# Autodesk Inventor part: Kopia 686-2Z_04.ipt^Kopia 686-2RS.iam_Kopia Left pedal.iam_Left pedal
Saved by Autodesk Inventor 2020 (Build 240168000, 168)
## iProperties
Created: 2017-10
Part Number: Kopia 686-2Z_04.ipt^Kopia 686-2RS.iam_Kopia Left pedal.iam_Left pedal
Material: Ogólny
Document SubType Name: Modeling
Designer: Tomasz
Density: 1 g/cm^3
Appearance: Domyślna
Sending System: SolidWorks 2017
Last Author: Tomasz
Last Saved: 2017-10-01
Author: Tomasz
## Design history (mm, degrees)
